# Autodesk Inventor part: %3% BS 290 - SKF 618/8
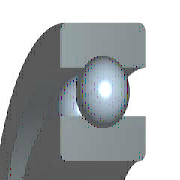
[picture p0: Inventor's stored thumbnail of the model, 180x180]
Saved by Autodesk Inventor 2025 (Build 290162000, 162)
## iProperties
Created: 2024-01
Part Number: %3% BS 290 - SKF 618/8
Material: Acciaio, Dolce
Description: Cuscinetti a sfere a fila singola
Document SubType Name: Modeling
Standard: BS 290
Designer: R5800u
Standards Organization: BSI
Language: it-IT
Size Designation: SKF 618/8
Categories: <MemberInstance><Categories><Category DisplayName="Parti albero" InternalName="7f7aeb1f-a693-4053-b835-cee3144e0d98" Mnemonic="SHFT"><Category DisplayName="Cusc
Density: 7.85 g/cm^3
Appearance: Semilucidato
IsCustomPart: 0
Author: R5800u
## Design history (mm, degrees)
node "WorkPoint1"
node "WorkAxis1"
node "WorkPlane3"
node "WorkPlane4"
node "WorkPoint2"
pattern_circular "Seriepolare1" dims "d17" = 79 (= msp_pocet), angle "d19" = 360 deg
body "Solid1"
node "Schizzo1"
revolve "Rivoluzione1" stored, may be unused: angle "d6" = 360 deg
revolve "Rivoluzione2" stored, may be unused: angle "d10" = 360 deg
node "Schizzo4"
revolve "Rivoluzione3" stored, may be unused: angle "d16" = 360 deg
fillet "Raccordo1" dims "d20" = 0.2 (= r)
sketch "Schizzo2"
  geometry: L1 (4, 4)-(8, 4); L2 (4, 0)-(4, 4); L3 (8, 0)-(4, 0); L4 (8, 4)-(8, 0); L5 (0, 0)-(0, 20); L6 (0, 0)-(0, 20); L7 (-7.2, 0)-(43.2, 0) reference
  constraints: 12 end point, 3 vertical, 2 horizontal, 1 collinear, 1 other
  dimensions: "d1" = 8 diameter of L1.start L5 (= Diam); "d3" = 16 diameter of L1.end L5 (= DD); "d5" = 4 distance of L2.start L1.start (= msp_mdtd2)
sketch "Schizzo3"
  geometry: L1 (6.72, 4)-(6.72, 2.96); L2 (5.28, 4)-(6.72, 4); L3 (5.28, 2.96)-(5.28, 4); L4 (5.28, 0)-(5.28, 1.04); L5 (6.72, 0)-(5.28, 0); L6 (6.72, 1.04)-(6.72, 0); L7 (8, 0)-(-8, 0) reference; L8 (8, 4)-(-8, 4) reference; L9 (0, -42.29)-(0, 61.29); L10 (0, 82.007)-(0, -63.007) reference; A1 r 1.2 centre (6, 2) between (6.72, 1.04) and (6.72, 2.96); A2 r 1.2 centre (6, 2) between (5.28, 2.96) and (5.28, 1.04)
  constraints: 14 end point, 4 collinear, 4 point on circle, 4 vertical, 2 centre point, 2 concentric, 2 horizontal, 2 point on line
  dimensions: "d9" = 2.4 diameter of A1 (= msp_mdtd6); "d21" = 5.28 distance between parallel lines of L9 L4 (= 0.5 x msp_d1); "d22" = 6 distance from line of L9 A1.centre (= 0.5 x msp_ds); "d23" = 6.72 distance between parallel lines of L9 L6 (= 0.5 x msp_dd1)
sketch "Schizzo5"
  geometry: L1 (6, 0.8)-(6, 3.2); L2 (6.72, 0)-(-6.72, 0) reference; L3 (6, 0.8)-(6, 3.2); A1 r 1.2 centre (6, 2) between (6, 0.8) and (6, 3.2); A2 r 1.2 centre (6, 2) between (6.72, 1.04) and (6.72, 2.96) reference
  constraints: 4 end point, 2 point on circle, 1 centre point, 1 concentric, 1 vertical
  dimensions: "d13" = 0 horizontal distance of A1.centre L1.start; "d15" = 2.4001 diameter of A1 (computed from msp_mdtd6)
other parameters: "Diam" = 8 [user parameter; used in 3 equation terms], "DD" = 16 [user parameter; used in 3 equation terms], "B" = 4 [user parameter; used in 1 equation term], "r" = 0.2 [user parameter; used in 1 equation term], "msp_ds" = 12 (= 0.5 x Diam + 0.5 x DD) [user parameter; used in 5 equation terms], "msp_d0" = 2.4 (= -0.3 x Diam + 0.3 x DD) [user parameter; used in 4 equation terms], "msp_d1" = 10.56 (= msp_ds - 0.6 x msp_d0) [user parameter; used in 1 equation term], "msp_dd1" = 13.44 (= msp_ds + 0.6 x msp_d0) [user parameter; used in 1 equation term], "msp_pom" = 18 (= 1.5 x msp_ds) [user parameter; used in 1 equation term], "msp_mdtd2" = 4 (= B) [user parameter; used in 3 equation terms], "msp_mdtd4" = 12 (= msp_ds) [user parameter], "msp_mdtd6" = 2.4 (= msp_d0) [user parameter; used in 2 equation terms], "msp_mdtd7" = 2 (= 0.5 x msp_mdtd2) [user parameter], "msp_pocet" = 79 (computed from msp_d0, msp_pom) [user parameter; used in 1 equation term], "d2" = 72 (derived), "d4" = 19 (derived), "d7" = 0, "d8" = 15.6 (derived), "d11" = -4 (computed from msp_mdtd2), "d12" = 0 (derived), "d14" = 15.6001 (derived), "d26" = 0, "d27" = 0, "d28" = 0, "d29" = 0, "d30" = 0
